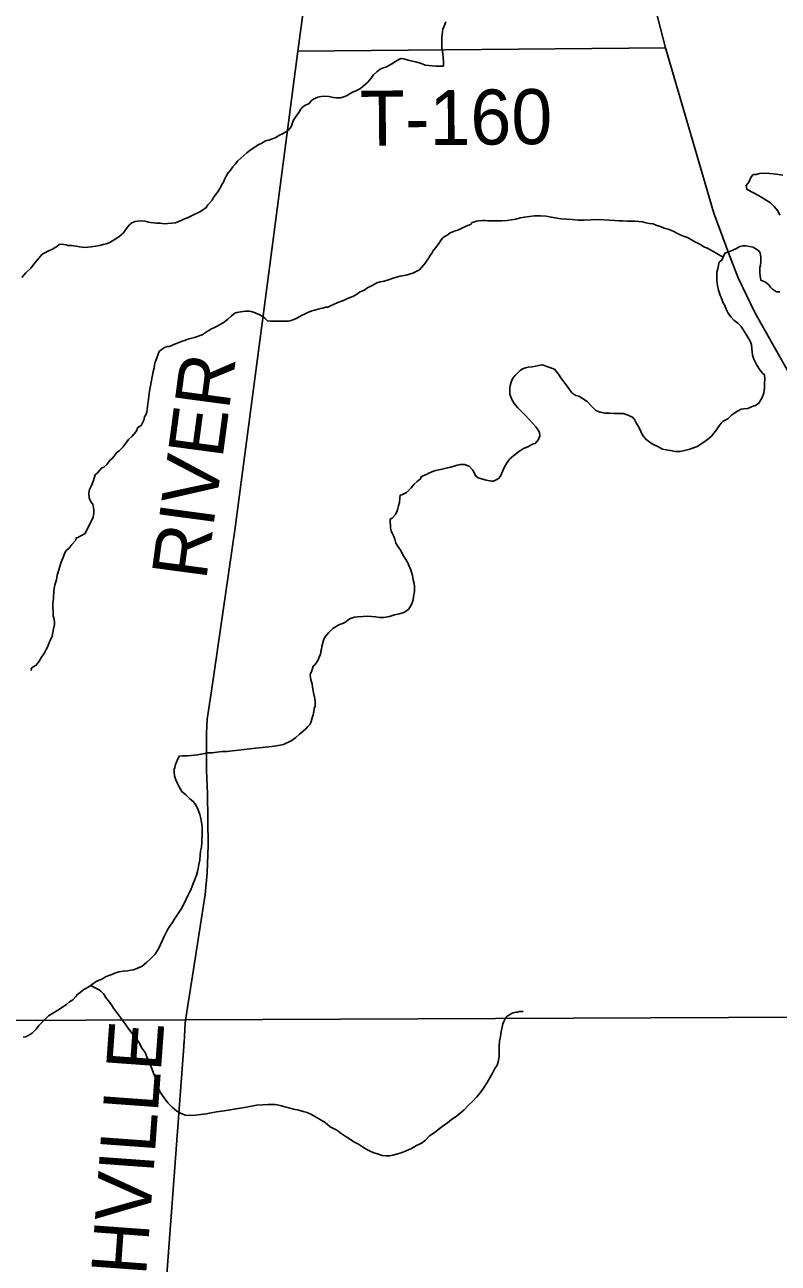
# Model space of a CAD drawing. Extents: x 0 to 34, y 0 to 22.
# Drawn here: x 2.447 to 3.225, y 15.108 to 16.386 of the extents above; entities that cross this region are included whole.
import ezdxf

# ---------------------------------------------------------------- set-up
doc = ezdxf.new("R2010")
doc.units = 0
for name, color, linetype in [('GM_X_Corporation', 7, 'Continuous'), ('GM_X_County_Road', 7, 'Continuous'), ('GM_X_County_Road_Text', 7, 'Continuous'), ('GM_X_Minor_River', 7, 'Continuous'), ('GM_X_Township_Road', 7, 'Continuous'), ('GM_X_Township_Road_Text', 7, 'Continuous')]:
    doc.layers.add(name, color=color, linetype=linetype)

msp = doc.modelspace()

# ---------------------------------------------------------------- linework, layer by layer
at = {"layer": 'GM_X_Corporation'}
msp.add_lwpolyline([(2.1, 20.3879), (2.1, 15.3574), (2.6127, 15.3592), (3.4135, 15.3624), (4.1534, 15.3654), (4.1554, 15.3654), (5.1944, 15.3696), (5.8313, 15.3671), (6.0415, 15.3685), (7.1072, 15.3824), (7.0838, 16.6084)], dxfattribs=at)
msp.add_lwpolyline([(2.1, 15.3574), (2.1, 14.1), (7.1335, 14.1), (7.1269, 14.4049), (7.1267, 14.4123), (7.1215, 14.6514), (7.118, 14.8105), (7.1072, 15.3824), (6.0415, 15.3685), (5.8313, 15.3671), (5.1944, 15.3696), (4.1554, 15.3654), (4.1534, 15.3654), (3.4135, 15.3624), (2.6127, 15.3592)], close=True, dxfattribs=at)
at = {"layer": 'GM_X_County_Road'}
for points in [[(2.6114, 15.3353), (2.6125, 15.3557), (2.613, 15.3586), (2.6211, 15.4109), (2.6332, 15.4885), (2.6352, 15.5106), (2.6362, 15.5391), (2.6358, 15.5923), (2.6347, 15.6162), (2.6345, 15.6549), (2.6354, 15.6694), (2.6399, 15.6987), (2.6639, 15.8643), (2.6992, 16.1326), (2.7288, 16.3587), (2.7486, 16.5041), (2.7949, 16.8713), (2.8402, 17.2336), (2.8523, 17.3349), (2.8513, 17.3497), (2.8493, 17.4814), (2.8475, 17.671), (2.8442, 17.8697)], [(2.5151, 14.1), (2.5162, 14.1138), (2.5215, 14.1876), (2.5299, 14.2946), (2.538, 14.3971), (2.5621, 14.6864), (2.5763, 14.8647), (2.5787, 14.884), (2.5909, 15.0595), (2.6111, 15.3314), (2.6113, 15.3344), (2.6114, 15.3353)]]:
    msp.add_lwpolyline(points, dxfattribs=at)
at = {"layer": 'GM_X_Minor_River'}
for points in [[(2.8817, 16.389), (2.8798, 16.3845), (2.8786, 16.3814), (2.8782, 16.3788), (2.8778, 16.3761), (2.8773, 16.3727), (2.8776, 16.3674), (2.8776, 16.3624), (2.8783, 16.3586), (2.8786, 16.3556), (2.879, 16.3522), (2.8793, 16.3476), (2.8793, 16.3453), (2.8793, 16.3434), (2.877, 16.3431), (2.8743, 16.3431), (2.8713, 16.3431), (2.8603, 16.3444), (2.8572, 16.3456), (2.8542, 16.3468), (2.8508, 16.3476), (2.847, 16.3484), (2.8428, 16.3496), (2.8383, 16.3508), (2.8353, 16.3512), (2.8307, 16.3486), (2.8257, 16.3456), (2.8203, 16.3426), (2.8161, 16.3411), (2.8138, 16.34), (2.8104, 16.3374), (2.8069, 16.3344), (2.8054, 16.3318), (2.8031, 16.3291), (2.8011, 16.3269), (2.7988, 16.3246), (2.7961, 16.3224), (2.7934, 16.3201), (2.7908, 16.319), (2.7881, 16.3175), (2.7854, 16.3164), (2.7827, 16.3149), (2.7797, 16.3131), (2.7762, 16.3116), (2.7728, 16.3105), (2.7686, 16.3105), (2.7656, 16.3109), (2.761, 16.3118), (2.7565, 16.3122), (2.7531, 16.3119), (2.7496, 16.3111), (2.747, 16.3104), (2.745, 16.3093), (2.7431, 16.3078), (2.7404, 16.3048), (2.7362, 16.3025), (2.7335, 16.3007), (2.732, 16.2988)], [(2.732, 16.2988), (2.73, 16.2954), (2.7246, 16.2882), (2.7235, 16.2848), (2.7219, 16.2807), (2.7188, 16.2769), (2.7165, 16.2754), (2.7131, 16.2736), (2.71, 16.2721), (2.7062, 16.2695), (2.7027, 16.2684), (2.7008, 16.2676), (2.6989, 16.2669), (2.6966, 16.2665), (2.6943, 16.2654), (2.6917, 16.2639), (2.6878, 16.2621), (2.6836, 16.2591), (2.6798, 16.2565), (2.6763, 16.2538), (2.6733, 16.2512), (2.6702, 16.2482), (2.6671, 16.2456), (2.6644, 16.2426), (2.6617, 16.2392), (2.6594, 16.2358), (2.6571, 16.2332), (2.6547, 16.229), (2.6532, 16.2264), (2.652, 16.2237), (2.6505, 16.2211), (2.6489, 16.2181), (2.6466, 16.2143), (2.6443, 16.2109), (2.6423, 16.2083), (2.6404, 16.2049), (2.6377, 16.2018), (2.6361, 16.2), (2.6342, 16.1973), (2.6304, 16.1947), (2.6277, 16.1928), (2.625, 16.1917), (2.622, 16.1902), (2.6185, 16.1884), (2.6151, 16.1869), (2.612, 16.1858), (2.6086, 16.1839), (2.6051, 16.1825), (2.6025, 16.1817), (2.5911, 16.1807), (2.5869, 16.1812), (2.5831, 16.1812), (2.58, 16.1816), (2.577, 16.182), (2.5747, 16.1824), (2.5728, 16.1828), (2.5709, 16.1833), (2.5675, 16.1837), (2.563, 16.1833), (2.5611, 16.183), (2.5576, 16.1815), (2.5553, 16.1796), (2.5526, 16.1766), (2.5491, 16.1713), (2.5441, 16.1672), (2.5403, 16.1646), (2.5376, 16.1631), (2.5349, 16.1613), (2.5311, 16.1598), (2.5281, 16.1591), (2.5246, 16.1583), (2.5201, 16.1576), (2.5155, 16.1569), (2.5121, 16.1566), (2.5086, 16.1562), (2.5064, 16.1563), (2.5037, 16.1567), (2.5003, 16.1575), (2.4973, 16.1579), (2.495, 16.1583), (2.4916, 16.1583), (2.4897, 16.1587), (2.4878, 16.1592), (2.4844, 16.1596), (2.4825, 16.1592), (2.4802, 16.1573), (2.4756, 16.1544), (2.471, 16.1525), (2.4679, 16.1506), (2.4652, 16.1492), (2.4618, 16.1454), (2.4579, 16.1405), (2.4533, 16.1349), (2.4483, 16.13), (2.444, 16.1251)], [(3.2292, 16.2309), (3.2223, 16.2318), (3.2159, 16.2326), (3.2098, 16.2327), (3.2052, 16.2324), (3.2018, 16.2316), (3.1988, 16.2313), (3.1968, 16.229), (3.1941, 16.2237), (3.1914, 16.22), (3.1921, 16.2162), (3.1963, 16.2138), (3.2004, 16.2119), (3.2042, 16.2099), (3.2076, 16.2076), (3.2121, 16.2049), (3.2166, 16.2022), (3.2204, 16.1984), (3.2242, 16.1941), (3.2264, 16.1895)], [(3.1679, 16.1463), (3.1515, 16.1555), (3.1484, 16.1566), (3.1447, 16.159), (3.1424, 16.1601), (3.1394, 16.1617), (3.1352, 16.164), (3.1311, 16.1663), (3.1269, 16.1679), (3.1235, 16.1691), (3.1205, 16.1706), (3.1175, 16.1722), (3.1144, 16.1738), (3.111, 16.1749), (3.1069, 16.1761), (3.1031, 16.1777), (3.0993, 16.1789), (3.0955, 16.1804), (3.0913, 16.1809), (3.0883, 16.1817), (3.0845, 16.1825), (3.0807, 16.1829), (3.0765, 16.1833), (3.0727, 16.1834), (3.0689, 16.1834), (3.064, 16.1835), (3.0602, 16.1835), (3.056, 16.184), (3.0389, 16.1849), (3.0317, 16.1846), (3.0245, 16.1843), (3.018, 16.1844), (3.0119, 16.1849), (3.0062, 16.1853), (3.0005, 16.1858), (2.9945, 16.1866), (2.9903, 16.1874), (2.985, 16.1886), (2.9793, 16.1887), (2.9732, 16.1887), (2.9679, 16.188), (2.9629, 16.1873), (2.9583, 16.1866), (2.9538, 16.1855), (2.9492, 16.1848), (2.945, 16.1841), (2.9393, 16.1838), (2.9347, 16.1835), (2.9309, 16.1835), (2.9275, 16.1836), (2.9249, 16.1836), (2.9222, 16.184), (2.9192, 16.1841), (2.9157, 16.1837), (2.9131, 16.1834), (2.9112, 16.1826), (2.9089, 16.1819), (2.9069, 16.18), (2.9027, 16.1782), (2.8982, 16.1759), (2.894, 16.1741), (2.8913, 16.1734), (2.8894, 16.1726), (2.8859, 16.1711), (2.884, 16.1697), (2.8817, 16.1682), (2.879, 16.1663), (2.8767, 16.164), (2.8736, 16.1591), (2.8709, 16.1557), (2.8682, 16.1524), (2.8671, 16.1501), (2.8655, 16.1478), (2.864, 16.1456), (2.8624, 16.1429), (2.8605, 16.1403), (2.8543, 16.1331), (2.8474, 16.1298), (2.8406, 16.1276), (2.8345, 16.1265), (2.8306, 16.1254), (2.8272, 16.1243), (2.8234, 16.1232), (2.8181, 16.1214), (2.8139, 16.1207), (2.8104, 16.1196), (2.8062, 16.1174), (2.8016, 16.1148), (2.7966, 16.1118), (2.7924, 16.1099), (2.7894, 16.1077), (2.7855, 16.1054), (2.7817, 16.1043), (2.7794, 16.1032), (2.776, 16.1014), (2.7703, 16.0992), (2.7657, 16.0973), (2.7626, 16.0958)], [(3.2262, 16.1105), (3.2228, 16.1105), (3.2186, 16.1132), (3.2167, 16.1151), (3.2145, 16.1178), (3.2115, 16.1202), (3.2085, 16.1217), (3.2066, 16.1225), (3.2059, 16.1267), (3.2055, 16.1301), (3.2055, 16.1328), (3.2056, 16.1354), (3.2064, 16.1377), (3.2068, 16.1419), (3.2068, 16.1461), (3.2058, 16.1506), (3.2043, 16.1529), (3.2009, 16.1552), (3.1986, 16.1564), (3.191, 16.158), (3.188, 16.1577), (3.1849, 16.157), (3.1807, 16.1547), (3.1754, 16.1525), (3.1716, 16.151), (3.1696, 16.1503), (3.1689, 16.1484), (3.1665, 16.1431), (3.1638, 16.1409)], [(3.1638, 16.1409), (3.163, 16.1378), (3.1622, 16.134), (3.1614, 16.1306), (3.1614, 16.1268), (3.1613, 16.1223), (3.162, 16.1169), (3.1631, 16.112), (3.1646, 16.107), (3.1664, 16.1028), (3.1679, 16.099), (3.1694, 16.0963), (3.1709, 16.0925), (3.1731, 16.0883), (3.1757, 16.0845), (3.1787, 16.081), (3.1828, 16.0779), (3.1862, 16.0745), (3.1933, 16.0637), (3.1955, 16.0595), (3.197, 16.0561), (3.1973, 16.0515), (3.1977, 16.0485), (3.198, 16.045), (3.1995, 16.0408), (3.2006, 16.0389), (3.2025, 16.0347), (3.2055, 16.0298), (3.2085, 16.0263), (3.2103, 16.0248), (3.2107, 16.0202), (3.2106, 16.0156), (3.2106, 16.0118), (3.2101, 16.0084), (3.2097, 16.0058), (3.2078, 16.0005), (3.2047, 15.9956), (3.2012, 15.9929), (3.1993, 15.9926), (3.1932, 15.99), (3.189, 15.9897), (3.1863, 15.9893), (3.1825, 15.9871), (3.1798, 15.9856), (3.1768, 15.9833), (3.1725, 15.9792), (3.1679, 15.977), (3.1656, 15.9747), (3.1637, 15.9721), (3.161, 15.9679), (3.1583, 15.9646), (3.1556, 15.9615), (3.1517, 15.9578), (3.1479, 15.9552), (3.141, 15.9507), (3.1361, 15.9489), (3.1322, 15.9478), (3.128, 15.9467), (3.1235, 15.9456), (3.1181, 15.9456), (3.1136, 15.9465), (3.109, 15.9473), (3.1053, 15.9481), (3.1026, 15.9492), (3.0996, 15.9512), (3.0954, 15.9528), (3.092, 15.9551), (3.0883, 15.9578), (3.086, 15.9608), (3.0838, 15.9639), (3.0819, 15.9685), (3.0797, 15.9723), (3.0782, 15.9746), (3.0763, 15.9785), (3.0741, 15.9811), (3.0688, 15.9835), (3.0646, 15.9847), (3.0597, 15.9847), (3.0551, 15.9848), (3.051, 15.9852), (3.0456, 15.9853), (3.0407, 15.9861), (3.0365, 15.988), (3.0324, 15.9919), (3.0275, 15.9973), (3.0226, 16.0004), (3.0189, 16.0027), (3.0158, 16.0035), (3.0136, 16.0047), (3.0117, 16.0062), (3.0091, 16.0097), (3.0057, 16.0143), (3.0023, 16.0189), (3.0001, 16.0215), (2.9978, 16.0254), (2.9937, 16.0304), (2.9809, 16.0351), (2.9774, 16.0344), (2.9744, 16.0336), (2.9706, 16.0329), (2.9664, 16.0326)], [(2.7626, 16.0958), (2.7599, 16.0947), (2.7573, 16.0944), (2.7546, 16.0936), (2.7523, 16.0933), (2.7497, 16.0926), (2.7462, 16.0915), (2.7432, 16.0907), (2.7393, 16.0889), (2.7359, 16.0874), (2.7332, 16.0863), (2.7302, 16.0844), (2.7263, 16.0826), (2.7221, 16.0807), (2.7191, 16.08), (2.7134, 16.0801), (2.7058, 16.0802), (2.7005, 16.0802), (2.6974, 16.0803), (2.6948, 16.0833), (2.6914, 16.0857), (2.6884, 16.0872), (2.6861, 16.088), (2.6842, 16.0892), (2.6808, 16.09), (2.6782, 16.0904), (2.6747, 16.0904), (2.6702, 16.0897), (2.666, 16.089), (2.6637, 16.0883), (2.6602, 16.0853), (2.6568, 16.0823), (2.6529, 16.0789), (2.6487, 16.0767), (2.6457, 16.0748), (2.643, 16.0737), (2.6399, 16.0722), (2.6365, 16.07), (2.6303, 16.0659), (2.6223, 16.0633), (2.6166, 16.0618), (2.6143, 16.0611), (2.6124, 16.06), (2.6094, 16.0593), (2.6071, 16.0585), (2.6044, 16.0574), (2.6002, 16.0556), (2.5964, 16.0541), (2.5945, 16.0541), (2.5918, 16.0534), (2.588, 16.0504), (2.5857, 16.0489), (2.5849, 16.0462), (2.5829, 16.0413), (2.5817, 16.0379), (2.5809, 16.0349), (2.5805, 16.0319), (2.5797, 16.0281), (2.5757, 16.008), (2.5752, 16.003), (2.5748, 15.9992), (2.574, 15.9951), (2.5736, 15.9913), (2.5735, 15.989), (2.5731, 15.9863), (2.572, 15.9833), (2.5708, 15.9814), (2.57, 15.978), (2.5673, 15.9723), (2.5638, 15.9705), (2.5622, 15.9663), (2.558, 15.9614), (2.5542, 15.958), (2.5515, 15.9543), (2.5484, 15.9501), (2.5445, 15.9464), (2.5418, 15.9441), (2.5399, 15.9419), (2.538, 15.9392), (2.5357, 15.937), (2.5334, 15.9347), (2.5318, 15.9321), (2.5287, 15.9295), (2.5261, 15.9283), (2.5222, 15.9235), (2.5199, 15.9216), (2.5179, 15.9155), (2.516, 15.9106), (2.514, 15.9064), (2.5132, 15.903), (2.5135, 15.8977), (2.5154, 15.8935), (2.5172, 15.8912), (2.518, 15.8878), (2.5183, 15.8851), (2.5183, 15.8821), (2.5178, 15.8779), (2.5093, 15.8609), (2.502, 15.8568), (2.5001, 15.8564), (2.4997, 15.8542)], [(2.9664, 16.0326), (2.9637, 16.0319), (2.9607, 16.0308), (2.9584, 16.0293), (2.9564, 16.027), (2.9533, 16.024), (2.9507, 16.0214), (2.9495, 16.0183), (2.9479, 16.0138), (2.9475, 16.0104), (2.9478, 16.0047), (2.9496, 15.9993), (2.9522, 15.9951), (2.956, 15.9905), (2.9594, 15.9871), (2.9635, 15.9832), (2.9676, 15.9786), (2.9714, 15.9744), (2.9744, 15.9709), (2.9766, 15.9682), (2.9781, 15.9652), (2.9785, 15.9617), (2.9773, 15.958), (2.9738, 15.9538), (2.9711, 15.9531), (2.9662, 15.9505), (2.9619, 15.9486), (2.9566, 15.9453), (2.9516, 15.9415), (2.9474, 15.9378), (2.9443, 15.9333), (2.9419, 15.9291), (2.938, 15.92), (2.9357, 15.9174), (2.9307, 15.9148), (2.9288, 15.9148), (2.9232, 15.916), (2.9148, 15.9184), (2.9122, 15.9203), (2.9107, 15.9238), (2.9092, 15.9265), (2.9055, 15.9303), (2.9009, 15.9323), (2.8967, 15.9323), (2.8933, 15.9316), (2.8903, 15.9305), (2.8864, 15.9294), (2.8819, 15.9283), (2.8777, 15.9272), (2.8742, 15.9265), (2.8712, 15.9258), (2.8689, 15.9254), (2.8666, 15.9243), (2.8639, 15.9232), (2.8616, 15.9217), (2.8597, 15.921), (2.8563, 15.9195), (2.8555, 15.9172), (2.8521, 15.9146), (2.849, 15.912), (2.8459, 15.9082), (2.8409, 15.9033), (2.8363, 15.9007), (2.8344, 15.9004), (2.834, 15.8977), (2.8339, 15.8931), (2.8327, 15.8894), (2.832, 15.8867), (2.8312, 15.8844), (2.8296, 15.8806), (2.8261, 15.8769), (2.8242, 15.8758), (2.8245, 15.8666), (2.8252, 15.8636), (2.8267, 15.8605), (2.8278, 15.8579), (2.8289, 15.8552), (2.83, 15.851), (2.833, 15.846), (2.8352, 15.8433), (2.8367, 15.8403), (2.8382, 15.8372), (2.8404, 15.8341), (2.8423, 15.8307), (2.8438, 15.8273), (2.8453, 15.8242), (2.846, 15.8212), (2.8471, 15.8177), (2.8478, 15.8132), (2.8489, 15.8093), (2.8492, 15.8063), (2.8492, 15.8044), (2.8492, 15.801), (2.8487, 15.7976), (2.8483, 15.7957), (2.8479, 15.793), (2.8471, 15.7904), (2.8464, 15.7885), (2.8452, 15.7858), (2.8429, 15.7824), (2.8383, 15.7794)], [(2.4997, 15.8542), (2.4958, 15.8496), (2.4924, 15.8455), (2.4897, 15.8433), (2.4885, 15.841), (2.4869, 15.8372), (2.4846, 15.8315), (2.4818, 15.8224), (2.4806, 15.8179), (2.4798, 15.8133), (2.479, 15.8111), (2.4782, 15.808), (2.4778, 15.8058), (2.477, 15.8024), (2.4769, 15.794), (2.4761, 15.7891), (2.4761, 15.7868), (2.4761, 15.7849), (2.4764, 15.7796), (2.4763, 15.7761), (2.4771, 15.7735), (2.4778, 15.7697), (2.4777, 15.767), (2.4769, 15.7624), (2.4753, 15.7549), (2.4737, 15.7511), (2.4726, 15.7492), (2.4706, 15.7435), (2.4691, 15.7412), (2.4675, 15.7378), (2.466, 15.7356), (2.4644, 15.7333), (2.4621, 15.7292), (2.459, 15.725), (2.4559, 15.7235), (2.454, 15.722), (2.4536, 15.7217), (2.454, 15.722), (2.4536, 15.7194)], [(2.8383, 15.7794), (2.8337, 15.778), (2.8287, 15.7769), (2.8234, 15.7754), (2.8177, 15.7744), (2.8131, 15.7744), (2.8093, 15.7748), (2.8048, 15.7753), (2.8006, 15.7757), (2.796, 15.7754), (2.7903, 15.7751), (2.7873, 15.7747), (2.7854, 15.774), (2.7831, 15.7732), (2.7808, 15.7718), (2.7785, 15.7699), (2.7766, 15.7688), (2.7743, 15.7677), (2.772, 15.7669), (2.7651, 15.7628), (2.7628, 15.7609), (2.7605, 15.7583), (2.7585, 15.7561), (2.7566, 15.7538), (2.7554, 15.7508), (2.7546, 15.7485), (2.7542, 15.7466), (2.7538, 15.7443), (2.7534, 15.7417), (2.7526, 15.739), (2.7522, 15.736), (2.751, 15.7337), (2.7503, 15.7314), (2.7487, 15.7288), (2.7468, 15.7258), (2.7448, 15.7239), (2.7441, 15.7216), (2.7429, 15.7182), (2.7421, 15.7163), (2.7417, 15.7144), (2.7424, 15.7103), (2.7435, 15.7053), (2.7442, 15.7003), (2.7453, 15.695), (2.7463, 15.6908), (2.7467, 15.687), (2.7466, 15.6828), (2.7458, 15.6802), (2.7454, 15.6771), (2.7446, 15.6737), (2.7438, 15.6707), (2.7426, 15.6669), (2.7415, 15.6643), (2.7392, 15.6616), (2.7372, 15.6594), (2.7345, 15.6568), (2.7307, 15.6538), (2.7269, 15.6504), (2.7226, 15.6474), (2.7192, 15.6455), (2.7169, 15.6444), (2.7142, 15.6433), (2.7108, 15.6426), (2.7047, 15.6415), (2.699, 15.6408), (2.6921, 15.6402), (2.6853, 15.6395), (2.6678, 15.6374), (2.6613, 15.6367), (2.656, 15.636), (2.6507, 15.6361), (2.6453, 15.6354), (2.6404, 15.6347), (2.6354, 15.6347), (2.6328, 15.634), (2.629, 15.6333), (2.6255, 15.6326), (2.6221, 15.6322), (2.6187, 15.6319), (2.6149, 15.6316), (2.6099, 15.6316), (2.6065, 15.6313), (2.6042, 15.6267), (2.6026, 15.6226), (2.6018, 15.6196), (2.6014, 15.6177), (2.6014, 15.6146), (2.6017, 15.6108), (2.6028, 15.6066), (2.6046, 15.6028), (2.6065, 15.5994), (2.6091, 15.5948), (2.6132, 15.5913), (2.617, 15.5874), (2.6211, 15.584), (2.6241, 15.5801), (2.626, 15.5756), (2.6278, 15.571), (2.6289, 15.5668), (2.6296, 15.5626), (2.63, 15.5584)], [(2.63, 15.5584), (2.6303, 15.5542), (2.6302, 15.5493), (2.6298, 15.5447), (2.6298, 15.5417), (2.6293, 15.5371), (2.6285, 15.533), (2.6281, 15.5292), (2.6276, 15.5238), (2.6268, 15.5193), (2.626, 15.5151), (2.6252, 15.5121), (2.6244, 15.5083), (2.6181, 15.4924), (2.6158, 15.4879), (2.6138, 15.4837), (2.6115, 15.4792), (2.6088, 15.4739), (2.6061, 15.4697), (2.6041, 15.4667), (2.6026, 15.4645), (2.6011, 15.4626), (2.5995, 15.4596), (2.5972, 15.4565), (2.5945, 15.452), (2.5925, 15.4486), (2.5906, 15.4445), (2.589, 15.4407), (2.5871, 15.4369), (2.5855, 15.4331), (2.5835, 15.4297), (2.5816, 15.4267), (2.5789, 15.4241), (2.5762, 15.4214), (2.5728, 15.4181), (2.5682, 15.4143), (2.5628, 15.4121), (2.5594, 15.4106), (2.5567, 15.4103), (2.5533, 15.4096), (2.5487, 15.4092), (2.5441, 15.4085), (2.5399, 15.4071), (2.5369, 15.4059), (2.5338, 15.4048), (2.5304, 15.4034), (2.5273, 15.4015), (2.5231, 15.3996), (2.5208, 15.3985), (2.5185, 15.397), (2.5158, 15.3952), (2.5124, 15.3929), (2.5101, 15.3914), (2.5082, 15.3903), (2.5063, 15.3888), (2.5043, 15.3873), (2.502, 15.3855), (2.4994, 15.3828), (2.4967, 15.3798), (2.4932, 15.3776), (2.4901, 15.375), (2.4863, 15.3723), (2.4829, 15.3701), (2.4714, 15.363), (2.4687, 15.3604), (2.4652, 15.3566), (2.4617, 15.3532), (2.459, 15.3495), (2.4552, 15.3457), (2.4529, 15.3442), (2.4506, 15.3427), (2.4479, 15.3416), (2.4456, 15.3413)], [(2.515, 15.3946), (2.5238, 15.3901), (2.5257, 15.3886), (2.5287, 15.3855), (2.5305, 15.3825), (2.5331, 15.379), (2.5365, 15.3744), (2.5387, 15.371), (2.5459, 15.3614), (2.5485, 15.3575), (2.5515, 15.3537), (2.5545, 15.3495), (2.5578, 15.3449), (2.5616, 15.3403), (2.5653, 15.3353), (2.5683, 15.3296), (2.5713, 15.3253), (2.5731, 15.3208), (2.5753, 15.3158), (2.5772, 15.3112), (2.5787, 15.3078), (2.5798, 15.304), (2.5812, 15.3005), (2.582, 15.2978), (2.5831, 15.294), (2.5845, 15.2895), (2.5867, 15.2845), (2.5909, 15.2784), (2.5946, 15.2734), (2.5991, 15.2688), (2.604, 15.2649), (2.6085, 15.2622), (2.6131, 15.2606), (2.6184, 15.2602), (2.6233, 15.2605), (2.6287, 15.2612), (2.6344, 15.2619), (2.6393, 15.263), (2.645, 15.264), (2.653, 15.2651), (2.6591, 15.2661), (2.6652, 15.2672), (2.6717, 15.2683), (2.6793, 15.2697), (2.6862, 15.2708), (2.6926, 15.2714), (2.698, 15.2718), (2.7022, 15.2717), (2.7052, 15.2717), (2.7075, 15.2713), (2.712, 15.2701), (2.7154, 15.2693), (2.7196, 15.2681), (2.7245, 15.2669), (2.7298, 15.2657), (2.7344, 15.2645), (2.7385, 15.2633), (2.7431, 15.2613), (2.7571, 15.2532), (2.7623, 15.2486), (2.7691, 15.2451), (2.7736, 15.2416), (2.7778, 15.2389), (2.7823, 15.2362), (2.7868, 15.2331), (2.7914, 15.2307), (2.7955, 15.228), (2.7993, 15.2257), (2.8035, 15.2234), (2.8072, 15.2218), (2.811, 15.2206), (2.8159, 15.219), (2.8201, 15.2186), (2.8235, 15.2186), (2.827, 15.2193), (2.8308, 15.2204), (2.8354, 15.2219), (2.8407, 15.2237), (2.8461, 15.2263), (2.8514, 15.2293), (2.8564, 15.2319), (2.8606, 15.2349), (2.8648, 15.2394), (2.8706, 15.2431), (2.8748, 15.2465), (2.879, 15.2495), (2.8833, 15.2528), (2.8875, 15.2562), (2.8921, 15.2592), (2.8963, 15.2626), (2.9005, 15.2663), (2.9051, 15.2708), (2.9094, 15.275), (2.9136, 15.2795), (2.9182, 15.2851), (2.9213, 15.2896), (2.9244, 15.2942)], [(2.9244, 15.2942), (2.9271, 15.2991), (2.9299, 15.304), (2.9322, 15.3089), (2.9345, 15.3123), (2.9357, 15.3157), (2.9365, 15.321), (2.9366, 15.3263), (2.9367, 15.3316), (2.9371, 15.3373), (2.9379, 15.3415), (2.9383, 15.3449), (2.9404, 15.3548), (2.9415, 15.3574), (2.9431, 15.3608), (2.945, 15.3627), (2.9473, 15.3642), (2.9492, 15.3657), (2.9511, 15.3664), (2.9538, 15.3668), (2.9557, 15.3671), (2.9576, 15.3675), (2.9603, 15.3675), (2.9614, 15.3675)]]:
    msp.add_lwpolyline(points, dxfattribs=at)
at = {"layer": 'GM_X_Township_Road'}
msp.add_line((2.7288, 16.3587), (3.1084, 16.3621), dxfattribs=at)
for points in [[(3.1744, 16.1479), (3.158, 16.1914), (3.1084, 16.3621), (3.0805, 16.4705), (3.0476, 16.5935), (3.0168, 16.7089), (2.9594, 16.9253), (2.8939, 17.1686), (2.857, 17.3063), (2.8523, 17.3349)], [(3.4143, 15.3325), (3.4137, 15.3619), (3.4134, 15.376), (3.4125, 15.4223), (3.4115, 15.4516), (3.4053, 15.4979), (3.3979, 15.531), (3.3803, 15.5903), (3.3406, 15.7584), (3.3205, 15.8469), (3.3112, 15.8759), (3.3014, 15.9006), (3.2789, 15.9459), (3.2368, 16.0243), (3.2004, 16.089), (3.1831, 16.1248), (3.1751, 16.1461), (3.1744, 16.1479)]]:
    msp.add_lwpolyline(points, dxfattribs=at)

# ---------------------------------------------------------------- texts
at = {"layer": 'GM_X_County_Road_Text'}
for s, rotation, p in [('RIVER', 82.3617, (2.6342, 15.8118)), ('FITCHVILLE', 85.8383, (2.5599, 14.9258))]:
    msp.add_text(s, height=0.05682, rotation=rotation, dxfattribs=at).set_placement(p)
at = {"layer": 'GM_X_Township_Road_Text'}
msp.add_text('T-160', height=0.05682, rotation=0.5614, dxfattribs=at).set_placement((2.7932, 16.261))

doc.saveas('drawing.dxf')
